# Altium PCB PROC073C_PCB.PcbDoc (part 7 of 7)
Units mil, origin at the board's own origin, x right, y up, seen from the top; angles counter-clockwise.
Board outline 2165.35 x 2695.12 mil, 8 copper layers (Top Layer, L2_GND, L3_SIGNAL 1, L4_SIGNAL 2, L5_SIGNAL 3, L6_SIGNAL 4, L7_GND, Bottom Layer), stack 55.9 mil thick; 393 components, 319 nets, 1311 pads, 1643 vias.
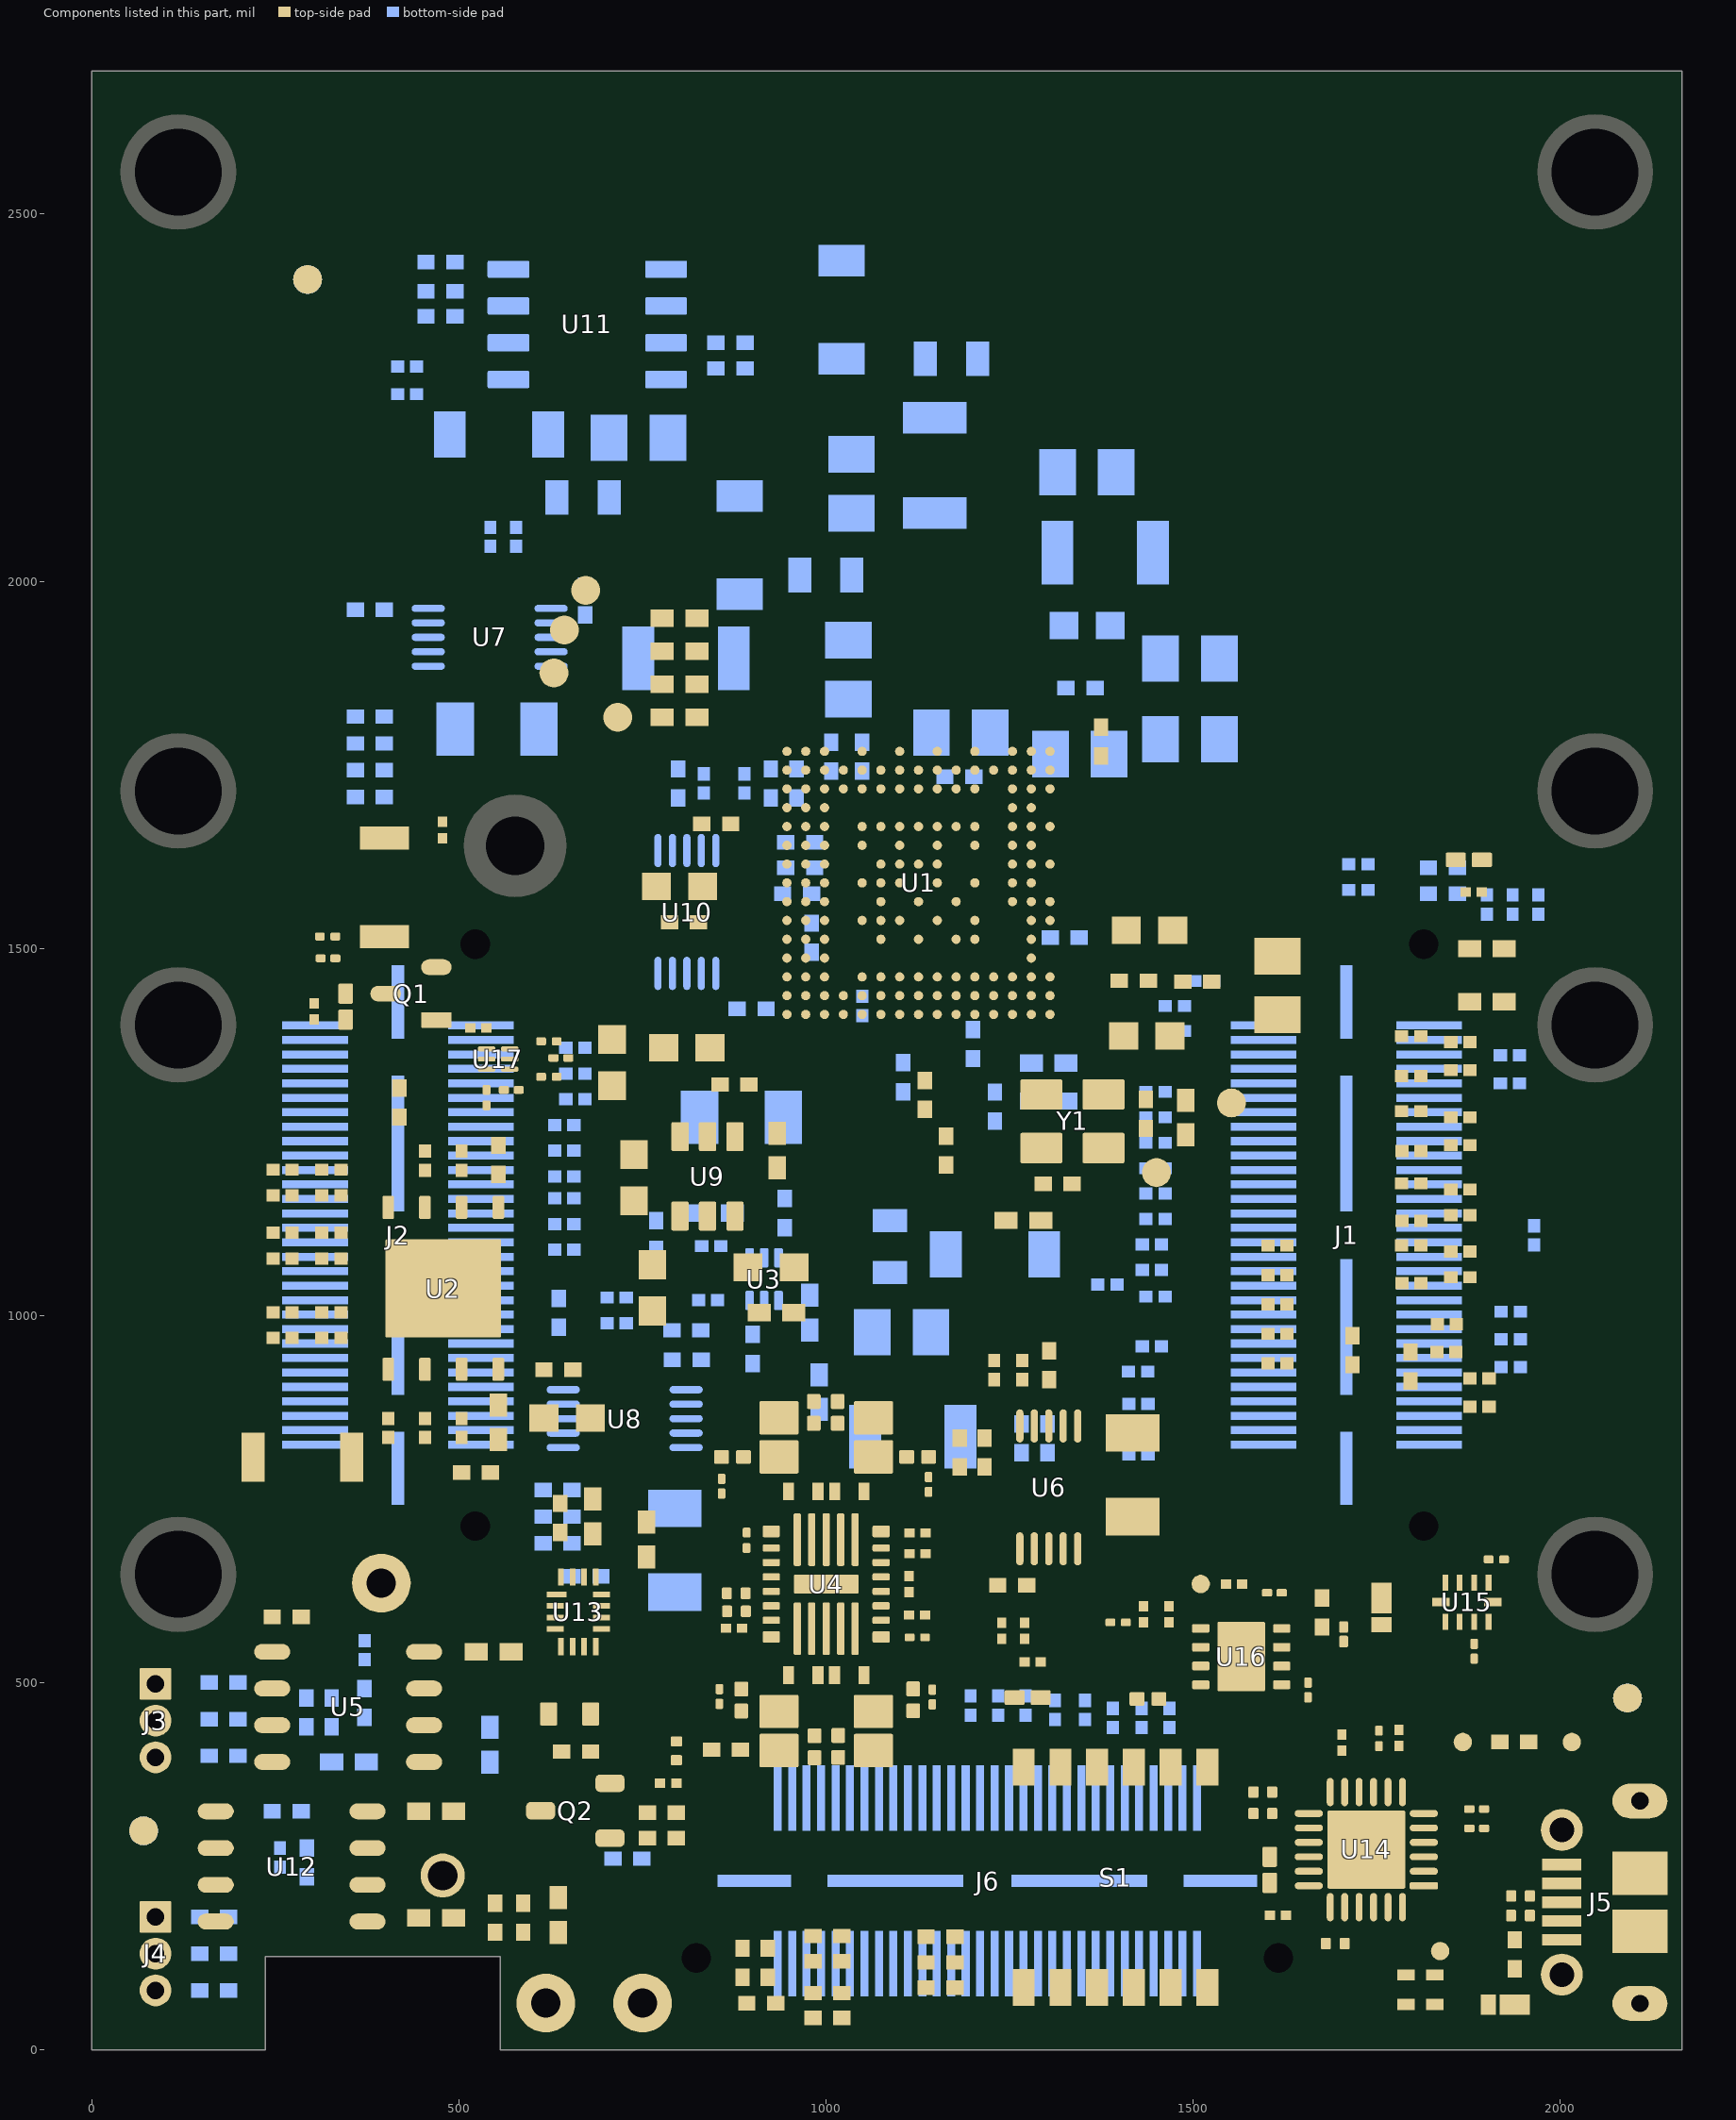
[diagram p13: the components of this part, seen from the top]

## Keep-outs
L2_GND:
  circle w1: c1074.8,1742.93 r7.87
  circle w1: c1177.16,1742.93 r7.87
  circle w1: c1125.98,1742.93 r7.87
  circle w1: c1279.52,1589.39 r7.87
  circle w1: c1279.52,1691.75 r7.87
  circle w1: c1279.52,1640.57 r7.87
  circle w1: c522.48,1506.29 r32
  circle w1: c1023.62,1742.93 r7.87
L3_SIGNAL 1:
  circle w1: c522.48,1506.29 r32
L5_SIGNAL 3:
  circle w1: c522.48,1506.29 r30
L7_GND:
  circle w1: c522.48,1505.29 r32
Bottom Layer:
  circle w1: c522.48,1506.29 r27.7
Keep-Out Layer:
  circle w1: c823.48,125.36 r32
  circle w1: c1616,125.36 r32
  circle w1: c522.48,1505.77 r32
  circle w1: c1813.86,1506.03 r32
  circle w1: c1813.86,713.51 r31
  circle w1: c522.48,713.25 r32
  lines w10: -5,-5 241.54,-5 241.54,122.3 551.54,122.3 551.54,-5 2170.35,-5 2170.35,2700.12 -5,2700.12 -5,-5
  text ".Layer_Name" at -423,-1328.72 h60

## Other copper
Top Layer:
  pour cut-out: 1039.36,1742.93 cw(c1023.62,1742.93) 1023.62,1727.19 cw(c1023.62,1742.93) 1007.88,1742.93 cw(c1023.62,1742.93) 1023.62,1758.67 cw(c1023.62,1742.93)
  pour cut-out: 1090.54,1742.93 cw(c1074.8,1742.93) 1074.8,1727.19 cw(c1074.8,1742.93) 1059.06,1742.93 cw(c1074.8,1742.93) 1074.8,1758.67 cw(c1074.8,1742.93)
  pour cut-out: 1141.72,1742.93 cw(c1125.98,1742.93) 1125.98,1727.19 cw(c1125.98,1742.93) 1110.24,1742.93 cw(c1125.98,1742.93) 1125.98,1758.67 cw(c1125.98,1742.93)
  pour cut-out: 1192.9,1742.93 cw(c1177.16,1742.93) 1177.16,1727.19 cw(c1177.16,1742.93) 1161.42,1742.93 cw(c1177.16,1742.93) 1177.16,1758.67 cw(c1177.16,1742.93)
  pour cut-out: 1295.26,1691.75 cw(c1279.52,1691.75) 1279.52,1676.01 cw(c1279.52,1691.75) 1263.78,1691.75 cw(c1279.52,1691.75) 1279.52,1707.49 cw(c1279.52,1691.75)
  pour cut-out: 1295.26,1640.57 cw(c1279.52,1640.57) 1279.52,1624.83 cw(c1279.52,1640.57) 1263.78,1640.57 cw(c1279.52,1640.57) 1279.52,1656.31 cw(c1279.52,1640.57)
  pour cut-out: 1295.26,1589.39 cw(c1279.52,1589.39) 1279.52,1573.65 cw(c1279.52,1589.39) 1263.78,1589.39 cw(c1279.52,1589.39) 1279.52,1605.13 cw(c1279.52,1589.39)
  text ".Layer_Name" at -423,-1328.72 h60
L2_GND:
  pour cut-out: 1031.49,1742.93 cw(c1023.62,1742.93) 1023.62,1735.06 cw(c1023.62,1742.93) 1015.75,1742.93 cw(c1023.62,1742.93) 1023.62,1750.8 cw(c1023.62,1742.93)
  pour cut-out: 1031.49,1742.93 cw(c1023.62,1742.93) 1023.62,1735.06 cw(c1023.62,1742.93) 1015.75,1742.93 cw(c1023.62,1742.93) 1023.62,1750.8 cw(c1023.62,1742.93)
  pour cut-out: 2140.93,1894.21 1997.92,1894.21 1885.11,1781.4 1885.11,1752.99 1682.7,1550.58 1621.63,1550.58 1392.37,1550.58 1354.68,1512.89 1354.68,1435.56 1354.68,1349.14 1374.9,1349.14 1374.9,1459.96 1374.9,1502.39 1400.28,1527.77 1691.88,1527.77 1908.35,1744.24 1908.35,1769.33 2011.45,1872.43 2140.93,1872.43
  pour cut-out: 1236.78,1369.53 1245.87,1378.63 1245.87,1390.9 1075.37,1561.4 1075.37,1583.56 1033,1625.93 1033,1675.19 1014.95,1693.24 977.13,1731.06 977.13,1803.28 809.63,1970.78 809.63,2674.62 788,2674.62 788,1960.17 956.28,1791.89 956.28,1718.82 1012.83,1662.27 1012.83,1612.65 1057.82,1567.66 1057.82,1548.49
  pour cut-out: 1250,1352.77 1236,1338.77 1236,1209.77 1257,1188.77 1257,1150.77 1263,1144.77 1320,1144.77 1344,1168.77 1403,1168.77 1411,1176.77 1411,1201.77 1433,1223.77 1462,1223.77 1470,1231.77 1470,1308.77 1435,1343.77 1373,1343.77 1373,1362.77 1454.66,1362.77 1486.15,1331.27 1486.15,1227.06 1465.09,1206 1444.23,1206 1426,1187.77 1426,1179.77 1397,1150.77 1354.51,1150.78 1329.44,1125.71 1257.05,1125.71 1236.03,1146.74 1236.02,1187.55 1216.02,1207.57 1216.02,1348.77 1230.01,1362.76 1249.76,1362.77
  pour cut-out: 1218.81,1203.66 1218.81,1187.87 1213.48,1182.54 1221.37,1174.65 1227.89,1174.65 1227.89,1179.98 1236.96,1189.06 1224.73,1201.29 1224.73,1203.07
  pour cut-out: 1029,1690.77 1044,1690.77 1044,1675.53 1041.24,1672.77 1023,1672.77 1023,1684.77
  pour cut-out: 1060,1506.93 1075,1506.93 1075,1491.7 1072.23,1488.93 1054,1488.93 1054,1500.93
  pour cut-out: 1085.74,1504.93 1100.74,1504.93 1100.74,1489.7 1097.97,1486.93 1079.74,1486.93 1079.74,1498.93
  pour cut-out: 1255,1524.93 1270,1524.93 1270,1509.7 1267.23,1506.93 1249,1506.93 1249,1518.93
  pour cut-out: 1023.84,1565.52 1023.84,1580.52 1039.07,1580.52 1041.84,1577.75 1041.84,1559.52 1029.84,1559.52
  pour cut-out: 1031,1630.93 1046,1630.93 1046,1615.7 1043.23,1612.93 1025,1612.93 1025,1624.93
  pour cut-out: 885,1561.12 900,1561.12 900,1545.88 897.23,1543.12 879,1543.12 879,1555.12
  pour cut-out: 1158.84,1677.77 1158.84,1692.77 1174.07,1692.77 1176.84,1690 1176.84,1671.77 1164.84,1671.77
  pour cut-out: 1225.74,1492.7 1240.95,1499.13 1243.46,1488.94 1244.87,1485.02 1229.98,1477.34 1225.59,1492.23
  pour cut-out: 1223.69,1493.92 1242.47,1501.17 1246.63,1484.33 1229.52,1475.52 1223.69,1493.14
  text ".Layer_Name" at -423,-1328.72 h60
L3_SIGNAL 1:
  pour cut-out: 1180.53,1695.24 1183,1692.77 1178.14,1687.91 1178.14,1674.63 1173.94,1670.44 1154.33,1670.44 1146.87,1677.9 1146.87,1683.84 1158.27,1695.24
  text ".Layer_Name" at -423,-1328.72 h60
L5_SIGNAL 3:
  text ".Layer_Name" at -423,-1328.72 h60
L7_GND:
  pour cut-out: 885.48,1168.36 885.48,1170.93 891.89,1177.34 897.35,1177.34 906.33,1168.36 898.95,1160.98 898.95,1158.1 895.1,1158.1 886.44,1166.76
  pour cut-out: 1743.38,938.01 1743.38,940.58 1749.79,946.99 1755.25,946.99 1764.23,938.01 1756.85,930.63 1756.85,927.75 1753,927.75 1744.34,936.41
  pour cut-out: 1048,1510.83 1021.98,1510.83 1021.98,1528.36 1048,1528.36
  pour cut-out: 1048.65,1562.03 1022.63,1562.03 1022.63,1579.56 1048.65,1579.56
  pour cut-out: 1022.8,1633.29 1048.81,1633.29 1048.81,1615.75 1022.8,1615.75
  pour cut-out: 1180.98,1673.77 1154.96,1673.77 1154.96,1691.31 1180.98,1691.31
  pour cut-out: 1064,1508.77 1080,1492.77 1080,1488.77 1071,1479.77 1068,1479.77 1052,1495.77 1052,1502.77 1059,1509.77 1062,1509.77
  text ".Layer_Name" at -423,-1328.72 h60
L4_SIGNAL 2:
  pour cut-out: 606.77,105.29 595.32,105.29 574.71,84.69 574.71,36.35 598.01,13.06 640.51,13.06 664.11,36.66 664.11,80.28 640.51,103.88
  text ".Layer_Name" at -423,-1328.72 h60
L6_SIGNAL 4:
  text ".Layer_Name" at -423,-1328.72 h60
Bottom Layer:
  pour cut-out: 263,2442.77 317,2496.77 880,2496.77 908,2468.77 908,2406.77 893,2391.77 274,2391.77 263,2402.77
  text ".Layer_Name" at -423,-1328.72 h60
Multi-Layer:
  pour cut-out: 211.71,19.19 211.71,154.89 586.6,154.89 586.6,19.19
  pour cut-out: 29.94,27.55 2140,27.55 2140,2673.77 30,2673.77 29.99,0 0,0 0,2695.13 2165.35,2695.12 2165.35,-0.01 29.94,0

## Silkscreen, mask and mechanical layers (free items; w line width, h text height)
Top Overlay:
  circle w10: c1851.26,218.12 r4.23
  rectangle: 24.14,216.24 52.92,231
  rectangle: 24.14,533.58 52.92,548.34
  lines w6: 180,744.77 220,744.77 220,644.77 ; 187.08,956.71 187.08,971.8 216.47,1001.19 ; 203.5,1206.1 198.92,1201.52 198.92,1095 214.76,1079.16 ; 359.1,939.04 371.21,951.15 371.21,991.64 364.91,997.95 ; 383.71,774.67 383.71,795.43 395.39,807.12 ; 522.4,204.96 527.4,209.97 527.4,213.05 ; 650.06,1337.19 662.26,1324.99 662.26,1238.78 ; 657.67,112.12 706.66,161.11 712.03,161.11 ; 675.82,2195.2 675.82,2041.71 744.05,2041.71 ; 761.66,2059.3 761.66,2193.97 ; 774.75,2062.58 794.98,2042.34 794.98,1983.12 ; 821.46,509.48 866.94,509.48 871.21,505.2 ; 890.13,517.17 902.42,504.88 932.08,504.88 ; 895.08,252.69 923.22,224.55 923.22,162.64 ; 1024.9,286.07 1033.92,277.05 1033.92,176.32 ; 1073.36,509.11 1102.17,509.11 1110.02,516.96 1152.89,516.96 1164.63,505.21 ; 1151.44,255.15 1173.87,232.72 1173.87,176.09 ; 1432.01,1236.14 1432.01,1218.99 1398.09,1185.07 ; 1432.32,544.63 1432.32,565.81 ; 1464.36,621.82 1464.36,635.6 1473.8,645.04 ; 1622.2,322.74 1630.02,330.56 1630.02,346.86 ; 1636.74,202.78 1651.26,188.26 1651.26,101.82 1647.25,97.82 ; 1750.24,113.65 1762.5,125.91 1811.19,125.91 1816.96,120.13 ; 1398.09,1185.07 1408.09,1185.07 1398.09,1195.07 1398.09,1185.07
  text "PROC073    REV C" at 306.02,1784.69 h45 r90
  text ".Layer_Name" at -423,-1328.72 h60
Bottom Overlay:
  circle w6: c1519.56,2258 r30
  circle w6: c696.91,1785.21 r30
  circle w6: c667.74,1444.28 r30
  circle w6: c306.34,2330.37 r30
  lines w6: 195.77,212.35 211.03,197.1 211.03,105.23 203.95,98.16 ; 230.93,1357.2 249.25,1375.52 ; 260.27,1989.62 367.53,1989.62 367.53,2282.85 ; 590.66,584.68 616.35,610.38 616.35,673.36 ; 618.56,1067.04 677.15,1067.04 677.71,1067.6 677.71,1262.72 698.6,1283.61 698.6,1390.14 638.79,1390.14 ; 722.34,1762.94 734.1,1751.18 775.46,1751.18 ; 779.7,1693.59 779.7,1764.78 949.23,1764.78 983.54,1799.1 1073.68,1799.1 1073.68,1727.91 1062.42,1716.64 997.88,1716.64 ; 849.15,976.93 869.4,956.68 869.4,912.82 ; 911.78,1611.9 925.28,1611.9 ; 915.72,1104.36 915.72,1171.8 ; 1466.32,2281.97 1437.37,2281.97 1437.37,2399.92 1681.03,2399.92 1681.03,2318.71 1681.03,2286.01 1570.18,2286.01 ; 1541.94,1998.64 1551.13,1989.45 1551.13,1951.61 ; 1864.28,1553.9 1864.28,1531.69 1900.82,1495.15 ; 1872.86,823.99 1888.58,808.27 1888.54,766.33 ; 1551.13,1951.61 1561.13,1961.61 1541.13,1961.61 1551.13,1951.61
  text "A" at 323.27,2314.67 h50
  text "B" at 1531.31,2241.14 h50
  text "B" at 708.67,1768.34 h50
  text "5V_IN" at 480.84,1549.08 h45
  text "A" at 684.67,1428.58 h50
  text "60" at 1938.04,1425.96 h60
  text "5V_IN" at 220.8,1394.53 h50 r270
  text "VPP_1P7" at 219.08,1201.14 h40 r270
  text "1V8" at 1546.29,889.46 h40
  text "1V2" at 1546.95,858.31 h40
  text "3V3" at 1939.64,839.01 h40
  text "1V0" at 1544.85,820.63 h40
  text "2" at 589.41,815.57 h40
  text "1" at 228.35,806.24 h40
  text "5V_IN" at 1957.22,730.57 h40
  text "1" at 1549.43,697.41 h60
  text "TEXAS" at 1484.42,658.92 h70
  text "INSTRUMENTS" at 1583.13,602.59 h70
  text ".Layer_Name" at -423,-1328.72 h60
Top Paste:
  text ".Layer_Name" at -423,-1328.72 h60
Bottom Paste:
  text ".Layer_Name" at -423,-1328.72 h60
Top Solder:
  rectangle: 33,2534.77 900,2673.77
  region: 170.16,1130.45 161.98,1122.27 161.98,1060.26 170.16,1053.01 170.16,737.97 208.1,700.03 208.1,549.95 30,549.95 30,2673.77 212.31,2673.77 212.31,1340.37 170.16,1298.22
  region: 1952.32,597.96 1966.41,583.86 1966.41,557.33 1973.96,549.78 2140,549.94 2140,2673.77 1960,2673.77 1960,1344.77 2015,1289.77 2015,774.77 1952.32,712.08
  text ".Layer_Name" at -423,-1328.72 h60
  text ".Layer_Name" at -423,-1328.72 h60
Bottom Solder:
  region: 1955.84,595.06 1967.77,583.13 1967.77,557.86 1975.39,550.25 2140,549.94 2140,2673.77 30,2673.77 30,549.95 214.94,549.95 215.12,719.64 170,764.76 170,1295.98 205,1330.98 205,1642.77 241,1678.77 241,2421.06 335.84,2515.9 1940,2515.9 1940,1748.77 2019.99,1668.77 2020,1500.76 1962.25,1443.02 1962.25,1357.17 2015.39,1304.03 2015.39,765.16 1955.85,705.61
  region: 1911.1,1755.67 1937.91,1755.3 2022.09,1671.12 2022.09,1664.79 2021.72,1664.42 1937.12,1664.42 1902.9,1698.64 1902.9,1747.47
  text ".Layer_Name" at -423,-1328.72 h60
Drill Guide:
  text ".Layer_Name" at -423,-1328.72 h60
M1 Board Outline:
  the board outline again, w10
  text ".Layer_Name" at -423,-1328.72 h60
M2 Board Dimensions:
  rectangle: -1000,-745.23 -875,-620.23
  rectangle: -875,-870.23 -500,-745.23
  lines w7: -1000,-745.23 0,-745.23 ; -875,-870.23 -875,-620.23 ; -750,-870.23 -750,-620.23 ; -500,-870.23 -500,-620.23 ; -250,-870.23 -250,-620.23 ; -1000,-870.23 0,-870.23 0,-620.23 -1000,-620.23 -1000,-870.23
  text ".Layer_Name" at -434.88,-1326.78 h60
M3 3D STEP Top:
  text ".Layer_Name" at -423,-1328.72 h60
M4 3D STEP Bottom:
  text ".Layer_Name" at -423,-1328.72 h60
M5 Assembly Top:
  lines w10: -1292,-1400.4 5308,-1400.4 ; -1292,-1197.06 5310,-1197.06 ; -1292,-993.73 -1292,-1603.73 2713,-1603.73 5310,-1603.73 5310,-993.73 -1291.5,-993.73 -1291.5,-1603.73 284,-1603.73 ; 1173,-1603.73 1173,-993.73 ; 2440,-1197.06 2440,-993.73 ; 3280,-1197.06 3280,-993.73 ; 3902,-1610.23 3902,-1407.4
  text "COMPONENTS MARKED 'DNP' SHOULD NOT BE POPULATED." at 153.5,-788.73 h60
  text "ASSEMBLY VARIANT:" at 153,-904.23 h60
  text ".VariantName" at 1189,-904.23 h60
  text "PCB VIEWED FROM TOP SIDE" at -1228.5,-1125.9 h60
  text "BOARD #:" at 1248,-1125.9 h60
  text ".PRJ_Number" at 1793.5,-1125.9 h60
  text "REV:" at 2638,-1125.9 h60
  text ".PCB_Rev" at 2929.5,-1125.9 h60
  text "SVN REV:" at 3476,-1125.9 h60
  text ".VersionControl_RevNumber" at 3982,-1125.9 h60
  text "Assembly Layer Top" at -433,-1325.23 h60
  text "TID #:" at 1248,-1329.23 h60
  text ".TID" at 1793.5,-1329.23 h60
  text "PLOT NAME =" at -1228.5,-1534.57 h60
  text ".plot_File_Name" at -423,-1534.57 h60
  text "GENERATED    :" at 1250,-1534.57 h60
  text ".Print_Date" at 2119.5,-1534.57 h60
  text ".Print_Time" at 2848.5,-1534.57 h60
  text "TEXAS INSTRUMENTS" at 4113,-1534.57 h60
M6 Assembly Bottom:
  lines w6: 705,1254.77 705,1394.77 ; 786.98,1167.48 791.01,1163.45 791.01,1113.45 810.46,1094 810.46,1101.2 802.41,1093.15 809.61,1093.15 ; 833.84,1760.54 833.84,1778.03 ; 1770.26,1663.38 1770.26,1605.73 1798.64,1577.34 1798.64,1587.22 1788.68,1577.25 1796.09,1577.25 ; 705,1394.77 714.25,1385.52 695.75,1385.52 705,1394.77
  lines w10: -1292.5,-1197.56 5309.5,-1197.56 ; -1290.5,-1400.9 5309.5,-1400.9 ; 115.5,-1610.73 115.5,-1407.9 ; 737.5,-1197.56 737.5,-994.23 ; 1577.5,-1197.56 1577.5,-994.23 ; 2844.5,-1604.23 2844.5,-994.23 ; 3733.5,-1604.23 5309,-1604.23 5309,-994.23 -1292.5,-994.23 -1292.5,-1604.23 1304.5,-1604.23 5309.5,-1604.23 5309.5,-994.23
  text "59" at 350,1394.77 h45
  text "60" at 530.04,1395.21 h45
  text "59" at 1636,1395.2 h45
  text "60" at 1821.54,1395.2 h45
  text "1" at 325,804.77 h45
  text "2" at 525,804.77 h45
  text "1" at 1611,794.77 h45
  text "2" at 1822,794.77 h45
  text "COMPONENTS MARKED 'DNP' SHOULD NOT BE POPULATED." at 5102,-788.23 h60
  text ".VariantName" at 4058,-904.23 h60
  text "ASSEMBLY VARIANT:" at 5097,-904.23 h60
  text ".VersionControl_RevNumber" at 35.5,-1126.4 h60
  text "SVN REV:" at 541.5,-1126.4 h60
  text ".PCB_Rev" at 1088,-1126.4 h60
  text "REV:" at 1379.5,-1126.4 h60
  text ".PRJ_Number" at 2224,-1126.4 h60
  text "BOARD #:" at 2769.5,-1126.4 h60
  text "PCB VIEWED FROM BOTTOM SIDE" at 5246,-1126.4 h60
  text "Assembly Bottom Layer" at 4885,-1315.23 h60
  text ".TID" at 2224,-1329.73 h60
  text "TID #:" at 2769.5,-1329.73 h60
  text "TEXAS INSTRUMENTS" at -95.5,-1535.07 h60
  text ".Print_Time" at 1169,-1535.07 h60
  text ".Print_Date" at 1898,-1535.07 h60
  text "GENERATED    :" at 2767.5,-1535.07 h60
  text ".plot_File_Name" at 4440.5,-1535.07 h60
  text "PLOT NAME =" at 5246,-1535.07 h60
M7 LPKF Text Top:
  lines w2: 1007.88,1742.93 1039.36,1742.93 ; 1015.75,1742.93 1031.49,1742.93 ; 1023.62,1727.19 1023.62,1758.67 ; 1023.62,1735.06 1023.62,1750.8
M9 Title Sheet:
  drawing of 57 lines, arcs and shapes, not listed
  text "1" at -260.16,7566.27 h70
  text "2" at 2235.5,7566.27 h70
  text "3" at 4724.84,7566.27 h70
  text "4" at 7231.51,7566.27 h70
  text "5" at 9730.5,7566.27 h70
  text "6" at 12235.5,7566.27 h70
  text "A" at -1416.5,6423.27 h70
  text "A" at 13383.5,6423.27 h70
  text "B" at -1416.5,4043.27 h70
  text "B" at 13383.5,4043.27 h70
  text "C" at -1416.5,1668.27 h70
  text "C" at 13383.5,1668.27 h70
  text "PROJECT TITLE:" at 10343.5,-192.73 h45
  text ".PRJ_Title" at 10393.5,-326.06 h70
  text "DESIGNED FOR:" at 10343.5,-493.73 h45
  text ".PRJ_Customer" at 10393.5,-633.73 h70
  text "D" at -1416.5,-701.73 h70
  text "D" at 13383.5,-701.73 h70
  text "FILE NAME:" at 10343.5,-793.73 h45
  text ".PCB_File_Name_No_Path" at 10393.5,-913.73 h70
  text "Texas Instruments (TI) and/or its licensors do not warrant the accuracy or completeness of this specification" at 5374,-1075.57 h45
  text "ENGINEER:" at 10343.5,-1083.73 h45
  text "LAYOUT BY:" at 11848.5,-1083.73 h45
  text "or any information contained therein. TI and/or its licensors do not warrant that this design will meet" at 5329.01,-1188.23 h45
  text ".PRJ_Engineer" at 10393.5,-1238.72 h70
  text ".PCB_Layout" at 11899,-1238.72 h70
  text "the specifications, will be suitable for your application or fit for any particular purpose, or will operate in" at 5329.01,-1300.9 h45
  text ".Layer_Name" at -413.7,-1335.71 h60
  text "ALTIUM DESIGNER VERSION:" at 11848.5,-1393.73 h45
  text "an implementation. TI and/or its licensors do not warrant that the design is production worthy. You should" at 5329.01,-1413.56 h45
  text "completely validate and test your design implementation to confirm the system functionality for your application." at 5374,-1526.23 h45
  text ".print_Scale" at 10393.5,-1527.06 h70
  text ".Application_BuildNumber" at 11899,-1527.06 h70
  text "1" at -260.16,-1733.73 h70
  text "2" at 2235.5,-1733.73 h70
  text "3" at 4724.84,-1733.73 h70
  text "4" at 7231.51,-1733.73 h70
  text "5" at 9730.5,-1733.73 h70
  text "WO # : 308145-8143-D" at 12235.5,-1733.73 h70
M10 Fab Notes:
  drawing of 198 lines, arcs and shapes, not listed
  text "DESIGN INFORMATION" at 11382.02,5885.94 h60
  text "MIN. TRACK WIDTH:" at 10737.46,5753.82 h60
  text "4" at 11833.7,5753.82 h60
  text "MIL" at 11988.46,5753.82 h60
  text "3.9" at 11781.69,5636.97 h60
  text "MIN. CLEARANCE:" at 10737.46,5629.69 h60
  text "MIL" at 11988.46,5629.69 h60
  text "MIN. VIA PAD SIZE:" at 10737.46,5505.57 h60
  text "13.77" at 11679,5500.77 h60
  text "MIL" at 12011,5496.77 h60
  text "EXTERNAL" at 12258.6,5378.26 h60
  text "0.0508mm (2.0MIL)" at 11432.46,5375.67 h60
  text "MINIMUM ANNULAR RING" at 10408.23,5367.44 h60
  text "PER" at 10608.23,5257.32 h60
  text "IPC-D-275 CLASS 2 LEVEL C" at 10828.23,5257.31 h60
  text "MIL, HOLES" at 12316.46,5156.84 h60
  text "+/-" at 11924,5148.25 h60
  text "+/-" at 12778,5148.25 h60
  text "REGISTRATION TOLERANCES:" at 10408.23,5147.19 h60
  text "METAL" at 11608,5147.19 h60
  text "5" at 12184.2,5147.19 h60
  text "3" at 13017.2,5147.19 h60
  text "MIL" at 13133.46,5147.19 h60
  text "HOLE SIZE TOLERANCE (UNLESS OTHERWISE SPECIFIED):" at 10408.23,5048.87 h60
  text "+/-" at 12778,5046 h60
  text "3" at 13017.2,5044.94 h60
  text "MIL" at 13133.46,5044.94 h60
  text "MATERIAL:" at 10333.46,4907.29 h60
  text "FR-4 High Tg" at 11319.9,4778.77 h60
  text "X" at 12062,4773.77 h60
  text "REFER STACK-UP" at 12562.85,4773.18 h55
  text "FR-408" at 10754.46,4766.26 h60
  text "OTHER" at 12242.46,4766.26 h60
  text "X" at 12233,4625.78 h60
  text "62 MIL (1.6mm) +/-10%" at 11074.56,4623.23 h60
  text "57.37 MIL +/-10%" at 12655,4616.77 h45
  text "THICKNESS:" at 10408.23,4615.01 h60
  text "OTHER" at 12359.46,4615.01 h60
  text "TOLERANCE:" at 10408.23,4476.69 h60
  text "X" at 11256.46,4476.69 h60
  text "ANSI IPC-6012 TYPE 3 CLASS 2" at 11434.48,4476.69 h60
  text "OTHER +/-" at 11434.46,4332.5 h60
  text "BOW & TWIST:" at 10408.23,4187.31 h60
  text "X" at 11256.46,4187.31 h60
  text "ANSI IPC-6012 TYPE 3 CLASS 2" at 11434.48,4187.31 h60
  text "OTHER +/-" at 11434.46,4040.62 h60
  text "DRILLING:" at 10333.46,3910 h60
  text "NC_DRILL FILES" at 12094.46,3804.81 h60
  text "REFERENCE:" at 10408.23,3800.87 h60
  text "X" at 11065.46,3800.78 h60
  text "AS SHOWN" at 11243.46,3800.87 h60
  text "X" at 11966.46,3800.87 h60
  text "OTHER" at 12392.46,3658.62 h60
  text "PTH COPPER THICKNESS:" at 10407.91,3655.09 h60
  text "X" at 11547.14,3655.09 h60
  text "20-30 um" at 11675.14,3655.09 h60
  text "BOARD FINISH:" at 10333.46,3507.5 h60
  text "SILKSCREEN:" at 10488.68,3397.37 h60
  text "X" at 11446.46,3397.37 h60
  text "TOP" at 11563.46,3397.37 h60
  text "X" at 11956.46,3397.37 h60
  text "BOTTOM" at 12074.46,3397.37 h60
  text "SILKSCREEN COLOR:" at 10488.68,3242.18 h60
  text "X" at 11445.46,3242.18 h60
  text "WHITE" at 11563.46,3242.18 h60
  text "OTHER" at 12074.46,3242.18 h60
  text "GREEN" at 11694.46,3098.73 h60
  text "X" at 12168.46,3098.73 h60
  text "OTHER" at 12312.46,3098.73 h60
  text "RED" at 12685,3098.73 h60
  text "SOLDER RESIST COLOR:" at 10488.68,3091.87 h60
  text "MATTE" at 11694.46,2944.48 h60
  text "SEMI-GLOSS" at 12312,2943.84 h60
  text "X" at 12168.06,2941.79 h60
  text "IMMERSION GOLD (ENIG)" at 11394.46,2771.71 h60
  text "ENEPIG" at 12732,2764.49 h60
  text "SURFACE FINISH:" at 10333.46,2763.49 h60
  text "IMM. TIN/SILVER OR EQUIV" at 10663,2626.17 h60
  text "X" at 10510,2623.49 h60
  text "OTHER" at 12094.46,2622.24 h60
  text "NOTES:" at 3534.49,2497.33 h60
  text "ARRAY/PANEL:" at 10333.46,2466.86 h60
  text "CUT AND TRIM PER M1 BOARD OUTLINE" at 11394.46,2458.64 h60
  text "N.C. ROUTE" at 11394.46,2322.67 h60
  text "X" at 12082.46,2322.67 h60
  text "V. SCORE" at 12260.46,2322.67 h60
  text "1. VIA'S ON PAD AND BGA PACKAGE AREA SHOULD BE FILLED WITH CONDUCTIVE MATERIAL AND SURFACE SHOULD BE FLAT" at 3563.63,2322.16 h60
  text "BGA AREA VIAS SHOULD BE CAPPED WITH COPPER PLATING TO ENSURE FLAT SURFACE" at 3670.36,2215.01 h60
  text "CERTIFICATION:" at 10333.46,2193.54 h60
  text "MATERIALS AND WORKMANSHIP FOR ALL PCBS" at 11058.46,2193.54 h60
  text "FLATNESS TOLERANCE FOR VIA ON PADS: +0.000 /- 0.001 INCHES ON BOTH SIDES." at 3670.36,2116.43 h60
  text "TO MEET OR EXCEED THE REQUIREMENTS OF:" at 11058.46,2099.48 h60
  text "OTHER THAN BGA AND VIA'S ON THE PAD  VIA FILLING REQUIREMENT CAN BE EXMPTED" at 3670.36,2006.42 h60
  text "X" at 10695.97,1970.85 h60
  text "ANSI IPC-A-600F CLASS ->" at 10823.96,1970.85 h60
  text "X" at 12471.97,1970.85 h60
  text "2" at 12581.96,1970.85 h60
  text "1" at 12266.96,1969.35 h60
  text "3" at 12935.96,1969.35 h60
  text "2. VENDOR MAY ADJUST SOLDERMASK WHEREVER SOLDERMASK PADS ARE THE SAME SIZE (1:1) AS PER THE MANUFACTURING CAPABILITIES" at 3563.63,1878.75 h60
  text "X" at 11507.97,1823.16 h60
  text "RoHS" at 11635.96,1823.16 h60
  text "OTHER" at 12280.36,1823.16 h60
  text "PER ORDER" at 12677.42,1823.16 h60
  text "AND ALL OTHER SOLDER MASK PADS SHALL NOT BE MODIFIED, PROVIDED NO ADJACENT COPPER IS EXPOSED AND NO CONFLICT IS PRODUCED" at 3670.36,1779.75 h60
  text "WITH ANY STATED \"VIA TENTING/COVERING\" REQUIREMENTS." at 3670.36,1686.47 h60
  text "ALL BOARDS MUST MEET OR EXCEED UL94-V0 REQUIREMENTS." at 10361,1669.34 h60
  text "PCB MUST BEAR THE UL94V-0 UL REGISTERED MATERIAL ID NUMBER" at 10361,1553.27 h60
  text "3. MANUFACTURER'S IDENTIFICATION,DATECODE LETTER SHALL BE SILKSCREENED ON SOLDER SIDE OF THE BOARD." at 3563.63,1525.38 h60
  text "ADDITIONAL REQUIREMENTS:" at 10333.46,1383.85 h60
  text "4. TRACE WIDTH SHOULD BE ACCURATELY ETCHED. MAX TOLERANCE +/- 1 MIL." at 3563.63,1375.21 h60
  text "MICROSECTION:" at 10408.23,1276.72 h60
  text "YES" at 11313.96,1276.72 h60
  text "5. LAYER TO LAYER REGISTRATION SHALL BE WITHIN +/-2 MIL." at 3563.63,1227.89 h60
  text "REQUIRED" at 12175.46,1132.39 h60
  text "BARE BOARD ELEC. TEST:" at 10408.23,1129.53 h60
  text "NONE" at 11713.96,1129.53 h60
  text "X" at 12057.46,1129.53 h60
  text "PER ORDER" at 12767.46,1129.53 h60
  text "6. REFER IMPEDANCE TABLE FOR IMPEDANCE CONTROL TRACES ON LAYER 1, 3, 6 & 8." at 3563.63,1083.43 h60
  text "XX MIL VIAS REQUIRE NON-CONDUCTIVE FILL AND PLANARIZE" at 10592,983.77 h59
  text "7. FOR ACCURACY OF THE ANTENNA DIMENSION, NEED TO BE MEASURE THE  ANTENNA DIMENSIONS ON ONE BAORD" at 3563.63,936.11 h60
  text "XX MIL VIAS REQUIRE CONDUCTIVE FILL AND PLANARIZE" at 10583,824.77 h60
  text "AS PER  ANTENNA DOCUMENT( Visio-IWR_60GHz4)." at 3670.36,815.7 h60
  text "OUTER XX MIL TRACES REQUIRE 50 OHM SINGLE-ENDED IMPEDANCE" at 10578.15,681.87 h58
  text "8. ALL VIAS ARE TENTED ON BOTH SIDES UNLESS OTHERWISE SOLDER MASK OPENED IN GERBER." at 3563.63,660.23 h60
  text "9. INTENTIONAL ONE NET ANTENNA VIA IS PRESENT IN DESIGN." at 3563.63,488.71 h60
  text "LAYER 1 & 6 (INNER LAYERS) XX MIL WIDE, XX MIL SPACE / TRACES REQUIRE 100 OHM DIFFERENTIAL IMPEDANCE" at 10617,431.77 h60
  text ".Layer_Name" at -425.59,-1329.35 h60
M11 Gerber Information:
  lines w10: -1292,-1400.4 5308,-1400.4 ; -1292,-1197.06 5310,-1197.06 ; -1292,-993.73 -1292,-1603.73 2713,-1603.73 5310,-1603.73 5310,-993.73 -1291.5,-993.73 -1291.5,-1603.73 284,-1603.73 ; 1173,-1603.73 1173,-993.73 ; 2440,-1197.06 2440,-993.73 ; 3280,-1197.06 3280,-993.73 ; 3902,-1610.23 3902,-1407.4
  text "ALL ARTWORK VIEWED FROM TOP SIDE" at -1228.5,-1125.9 h60
  text "BOARD #:" at 1248,-1125.9 h60
  text ".PRJ_Number" at 1793.5,-1125.9 h60
  text "REV:" at 2638,-1125.9 h60
  text ".PCB_Rev" at 2929.5,-1125.9 h60
  text "SVN REV:" at 3476,-1125.9 h60
  text ".VersionControl_RevNumber" at 3982,-1125.9 h60
  text "LAYER NAME =" at -1228.5,-1328.72 h60
  text "TID #:" at 1248,-1329.23 h60
  text ".TID" at 1793.5,-1329.23 h60
  text "PLOT NAME =" at -1228.5,-1534.57 h60
  text ".plot_File_Name" at -423,-1534.57 h60
  text "GENERATED    :" at 1250,-1534.57 h60
  text ".Print_Date" at 2119.5,-1534.57 h60
  text ".Print_Time" at 2848.5,-1534.57 h60
  text "TEXAS INSTRUMENTS" at 4113,-1534.57 h60
M12 Stackup:
  drawing of 562 lines, arcs and shapes, not listed
  text "LAYER STACK-UP :" at 5193.51,7078.8 h80
  text "Layer" at 5213.16,6908.54 h60
  text "Name" at 5623.08,6908.54 h60
  text "Material" at 6552.82,6908.54 h60
  text "Thickness" at 7412.59,6908.54 h60
  text "Constant" at 8062.42,6908.54 h60
  text "Board Layer Stack" at 8632.29,6908.54 h60
  text "1" at 5213.16,6788.54 h60
  text "Top Overlay" at 5623.08,6788.54 h60
  text "2" at 5213.16,6668.54 h60
  text "Top Solder" at 5623.08,6668.54 h60
  text "Solder Resist" at 6552.82,6668.54 h60
  text "0.80mil" at 7412.59,6668.54 h60
  text "1" at 8062.42,6668.54 h60
  text "6" at 5023.59,6549.65 h60
  text "3" at 5213.16,6548.54 h60
  text "Top Layer" at 5623.08,6548.54 h60
  text "Copper" at 6552.82,6548.54 h60
  text "1.60mil" at 7412.59,6548.54 h60
  text "4" at 5213.16,6428.54 h60
  text "Dielectric 1" at 5623.08,6428.54 h60
  text "RO4835 LOPRO" at 6552.82,6428.54 h60
  text "3.90mil" at 7412.59,6428.54 h60
  text "3.5" at 8062.42,6428.54 h60
  text "5" at 5213.16,6308.54 h60
  text "L2_GND" at 5623.08,6308.54 h60
  text "Copper" at 6552.82,6308.54 h60
  text "1.40mil" at 7412.59,6308.54 h60
  text "6" at 5213.16,6188.54 h60
  text "Dielectric 2" at 5623.08,6188.54 h60
  text "PCL370HR" at 6552.82,6188.54 h60
  text "5.50mil" at 7412.59,6188.54 h60
  text "4.17" at 8062.42,6188.54 h60
  text "6" at 5019.85,6071.38 h60
  text "7" at 5213.16,6068.54 h60
  text "L3_SIGNAL 1" at 5623.08,6068.54 h60
  text "Copper" at 6552.82,6068.54 h60
  text "1.40mil" at 7412.59,6068.54 h60
  text "8" at 5213.16,5948.54 h60
  text "Dielectric 3" at 5623.08,5948.54 h60
  text "PCL370HR" at 6552.82,5948.54 h60
  text "10.00mil" at 7412.59,5948.54 h60
  text "4.17" at 8062.42,5948.54 h60
  text "9" at 5213.16,5828.54 h60
  text "L4_SIGNAL 2" at 5623.08,5828.54 h60
  text "Copper" at 6552.82,5828.54 h60
  text "1.40mil" at 7412.59,5828.54 h60
  text "10" at 5213.16,5708.54 h60
  text "Dielectric 4" at 5623.08,5708.54 h60
  text "PCL370HR" at 6552.82,5708.54 h60
  text "5.50mil" at 7412.59,5708.54 h60
  text "4.17" at 8062.42,5708.54 h60
  text "11" at 5213.16,5588.54 h60
  text "L5_SIGNAL 3" at 5623.08,5588.54 h60
  text "Copper" at 6552.82,5588.54 h60
  text "1.40mil" at 7412.59,5588.54 h60
  text "12" at 5213.16,5468.54 h60
  text "Dielectric 5" at 5623.08,5468.54 h60
  text "PCL370HR" at 6552.82,5468.54 h60
  text "10.00mil" at 7412.59,5468.54 h60
  text "4.17" at 8062.42,5468.54 h60
  text "13" at 5213.16,5348.54 h60
  text "L6_SIGNAL 4" at 5623.08,5348.54 h60
  text "Copper" at 6552.82,5348.54 h60
  text "1.40mil" at 7412.59,5348.54 h60
  text "6" at 5022.17,5345.68 h60
  text "14" at 5213.16,5228.54 h60
  text "Dielectric 6" at 5623.08,5228.54 h60
  text "PCL370HR" at 6552.82,5228.54 h60
  text "5.50mil" at 7412.59,5228.54 h60
  text "4.17" at 8062.42,5228.54 h60
  text "15" at 5213.16,5108.54 h60
  text "L7_GND" at 5623.08,5108.54 h60
  text "Copper" at 6552.82,5108.54 h60
  text "1.40mil" at 7412.59,5108.54 h60
  text "16" at 5213.16,4988.54 h60
  text "Dielectric 7" at 5623.08,4988.54 h60
  text "PCL370HR" at 6552.82,4988.54 h60
  text "3.90mil" at 7412.59,4988.54 h60
  text "4.17" at 8062.42,4988.54 h60
  text "17" at 5213.16,4868.54 h60
  text "Bottom Layer" at 5623.08,4868.54 h60
  text "Copper" at 6552.82,4868.54 h60
  text "1.60mil" at 7412.59,4868.54 h60
  text "6" at 5025.35,4866.09 h60
  text "18" at 5213.16,4748.54 h60
  text "Bottom Solder" at 5623.08,4748.54 h60
  text "Solder Resist" at 6552.82,4748.54 h60
  text "0.80mil" at 7412.59,4748.54 h60
  text "1" at 8062.42,4748.54 h60
  text "19" at 5213.16,4628.54 h60
  text "Bottom Overlay" at 5623.08,4628.54 h60
  text "NOTE :" at 5225.04,4478.82 h60
  text "1. THIS IS AN IMPEDANCE CONTROLLED BOARD." at 5408.55,4373.8 h60
  text "2. EXTERNAL LAYER CU THICKNESSES ARE FINISHED THICKNESS AFTER PLATING." at 5408.55,4275.93 h60
  text "6" at 7261.89,4055.48 h60
  text "IMPEDANCE TABLE :" at 6105.5,4040.1 h80
  text "SPACING" at 6299.43,3884.35 h70
  text "LAYER" at 5549.43,3879.35 h70
  text "TRACE WIDTH" at 5814.43,3879.35 h70
  text "IMPEDANCE +/- 10%" at 6634.43,3879.35 h70
  text "REFERENCE LAYER" at 7359.43,3879.35 h70
  text "TOP" at 5584.43,3729.35 h70
  text "7.795 MILS" at 5869.43,3724.35 h65
  text "8 MILS" at 6324.43,3724.35 h65
  text "50 OHM" at 6744.43,3724.35 h65
  text "LAYER-2 (GND LAYER)" at 7309.43,3724.35 h65
  text "LAYER" at 5564.57,3510.28 h70
  text "TRACE WIDTH" at 5851.77,3509.43 h70
  text "SPACING" at 6336.77,3509.43 h70
  text "IMPEDANCE +/- 10%" at 6671.77,3509.43 h70
  text "REFERENCE LAYER" at 7396.77,3509.43 h70
  text "LAYER-2 AND" at 7510.74,3369.43 h65
  text "TOP AND" at 5529.48,3365.58 h70
  text "5.2 MILS" at 5952.73,3349.43 h65
  text "5 MILS" at 6385.52,3349.43 h65
  text "100 OHM" at 6853.75,3349.43 h65
  text "BOTTOM" at 5555.85,3296.89 h60
  text "LAYER-7" at 7581.18,3294.43 h65
  text "LAYER-2, LAYER 4 &" at 7412.84,3192.75 h65
  text "4.8 MILS" at 5951.98,3159.52 h65
  text "7.2 MIL" at 6380.02,3159.52 h65
  text "100 OHM" at 6853.75,3159.52 h65
  text "L3 & L6" at 5558.48,3158.06 h70
  text "LAYER-5, LAYER 7" at 7442.71,3122.36 h65
  text ".Layer_Name" at -423,-1328.72 h60
M13 Component Bodies Top:
  text ".Layer_Name" at -423,-1328.72 h60
M14 Component Bodies Bottom:
  text ".Layer_Name" at -423,-1328.72 h60
M15 Courtyards Top:
  text ".Layer_Name" at -423,-1328.72 h60
M16 Courtyards Bottom:
  text "NOTES: UNLESS OTHERWISE SPECIFIED." at 4550.94,4101.82 h60
  text "1. FABRICATE PER IPC-6012A CLASS 2." at 4550.94,3948.7 h60
  text "2. FOR BOARD THICKNESS AND IMPEDANCE DETAILS REFER STACKUP DOCUMENT." at 4550.94,3839.82 h60
  text "3. PRINTED WIRING BOARD SHALL COMPLY WITH REQUIREMENTS OF ANSI/J-STD-003." at 4550.94,3722.82 h60
  text "4. SURFACE FINISH:IMMERSION SILVER" at 4550.94,3606.82 h60
  text "5. SOLDERMASK ON BOTH SIDES OF THE BOARD SHALL BE LPI, COLOR RED." at 4550.94,3488.82 h60
  text "6. SILK SCREEN LEGEND TO BE APPLIED PER LAYER STACKUP USING WHITE" at 4550.94,3359.82 h60
  text "NON-CONDUCTIVE EPOXY INK." at 4670.94,3246.82 h60
  text "7. THIS PRINTED WIRING BOARD IS DESIGNED WITH A MINIMUM CONDUCTOR" at 4550.94,3126.82 h60
  text "WIDTH AND SPACING OF 4 MIL &  4 MILS." at 4720.94,3003.82 h60
  text "8. ALL VIAS ARE TENTED ON BOTH SIDES UNLESS SOLDERMASK OPENED IN GERBER." at 4550.94,2889.82 h60
  text "9. ALL VIAS ON PAD INCLUDING BGA AREA SHOULD BE FILLED WITH NON CONDUCTIVE EPOXY AND SURFACE SHOULD BE FLAT" at 4550.94,2740.82 h60
  text "BGA AREA VIAS SHOULD BE CAPPED WITH COPPER PLATING TO ENSURE FLAT SURFACE" at 4720.94,2633.82 h60
  text "REFER VIA FILL DOCUMENT TO IDENTIFY THE VIAS TO BE FILLED" at 4720.94,2529.82 h60
  text "FLATNESS TOLERANCE FOR VIA ON PADS: +0.000 /- 0.001 INCHES ON BOTH SIDES." at 4720.94,2420.82 h60
  text "10. SOLDER MASK OPENING IS KEPT SAME SIZE AS PAD (1:1)" at 4550.94,2300.82 h60
  text "THE MANUFACTURER IS REQUESTED TO RESIZE IT AS PER THEIR SOLDERMASK TOLERANCE EXCEPT NPTH DRILL AND FIDUCIALS." at 4720.94,2198.82 h60
  text "11. VENDOR SHOULD FOLLOW ROHS COMPLIANT PROCESS AND Pb FREE FOR MANUFACTURING" at 4564.94,2093.82 h60
  text "12. MANUFACTURER'S IDENTIFICATION,DATECODE LETTER SHALL BE SILKSCREENED ON SOLDER SIDE" at 4564.94,1968.82 h60
  text "OF THE BOARD." at 4734.94,1855.82 h60
  text "13. TRACE WIDTH SHOULD BE ACCURATELY ETCHED. MAX TOLERANCE +/- 1 MIL" at 4564.94,1741.82 h60
  text "14. BOARD DIMENSIONS ARE IN MM)." at 4564.94,1602.82 h60
  text "15. BOW AND TWIST SHALL NOT EXCEED 0.7% OF LONGEST SIDE" at 4564.94,1460.82 h60
  text "16. PCB Material must meet or exceed UL94V-0 requirements." at 4564.94,1313.82 h60
  text "PCB must bear the UL94V-0 registered material ID number." at 4734.94,1211.82 h60
  text "17. LAYER TO LAYER REGISTRATION SHALL BE WITHIN +/-2 MIL" at 4564.94,1071.82 h60
  text "18. REFER STACKUP DOCUMENT FOR IMPEDANCE CONTROL TRACES ON LAYER 1." at 4564.94,933.82 h60
  text "50 OHM SINGLE ENDED AND 10OHM DIFFERENTIAL IMPEDANCE CONTROL TRACES." at 4734.94,834.82 h60
  text ".Layer_Name" at -423,-1328.72 h60
Drill Drawing:
  lines w8: -1243.55,3986.49 -1116.65,3986.49 -1116.65,4105.2 -1243.55,4105.2 -1243.55,3986.49 ; -1241.47,6087.39 -1114.58,6087.39 -1114.58,6206.09 -1241.47,6206.09 -1241.47,6087.39 ; -1241.47,6246.5 -1114.58,6246.5 -1114.58,6365.21 -1241.47,6365.21 -1241.47,6246.5 ; -1241.47,6420.23 -1114.58,6420.23 -1114.58,6538.94 -1241.47,6538.94 -1241.47,6420.23 ; -1241.47,6575.57 -1241.47,6694.27 -1114.58,6694.27 -1114.58,6575.57 -1241.47,6575.57
  lines w15: -1094.8,3966.86 4409.91,3966.86 ; -1094.8,4132.62 4409.91,4132.62 ; -1048.99,4912.4 4642.15,4912.4 ; -1048.99,6735.76 4642.15,6735.76 ; -644.32,3801.1 -644.32,4298.38 ; -598.51,4746.64 -598.51,6901.52 ; -165.78,3801.1 -165.78,4298.38 ; -119.97,4746.64 -119.97,6901.52 ; 682.97,3801.1 682.97,4298.38 ; 728.78,4746.64 728.78,6901.52 ; 1028.49,3801.1 1028.49,4298.38 ; 1074.3,4746.64 1074.3,6901.52 ; 1528.7,3801.1 1528.7,4298.38 ; 1574.51,4746.64 1574.51,6901.52 ; 2274.89,3801.1 2274.89,4298.38 ; 2323.69,4746.64 2323.69,6901.52 ; 3078,3801.1 3078,4298.38 ; 3126.8,4746.64 3126.8,6901.52 ; 3860.33,3801.1 3860.33,4298.38 ; 4092.57,4746.64 4092.57,6901.52 ; -1094.8,3801.1 4409.91,3801.1 4409.91,4298.38 -1094.8,4298.38 -1094.8,3801.1 ; -1048.99,4746.64 4642.15,4746.64 4642.15,6901.52 -1048.99,6901.52 -1048.99,4746.64
  text "Drill Table: Top Layer to Bottom Layer" at -969.67,6950.88 h80
  text "Symbol" at -949.54,6785.49 h96
  text "Hit Count" at -548.78,6785.49 h96
  text "Finished Hole Size" at -70.24,6785.49 h96
  text "Plated" at 778.51,6785.49 h96
  text "Hole Type" at 1124.03,6785.49 h96
  text "Physical Length" at 1624.24,6785.49 h96
  text "Rout Path Length" at 2373.42,6785.49 h96
  text "Drill Layer Pair" at 3176.53,6785.49 h96
  text "Tolerance" at 4142.3,6785.49 h96
  text "16" at -548.78,6619.73 h80
  text "7.87mil (0.200mm)" at -70.24,6619.73 h80
  text "PTH" at 778.51,6619.73 h80
  text "Round" at 1124.03,6619.73 h80
  text "-" at 1624.24,6619.73 h80
  text "-" at 2373.42,6619.73 h80
  text "Top Layer - Bottom Layer" at 3176.53,6619.73 h80
  text "+0/-7.874mil" at 4142.3,6619.73 h80
  text "B" at -984.4,6604.74 h73.67
  text "8" at -1204.47,6594.48 h80
  text "74" at -548.78,6453.97 h80
  text "8.00mil (0.203mm)" at -70.24,6453.97 h80
  text "PTH" at 778.51,6453.97 h80
  text "Round" at 1124.03,6453.97 h80
  text "-" at 1624.24,6453.97 h80
  text "-" at 2373.42,6453.97 h80
  text "Top Layer - Bottom Layer" at 3176.53,6453.97 h80
  text "+0/-8mil" at 4142.3,6453.97 h80
  text "8" at -1204.47,6439.15 h80
  text "C" at -984.4,6438.98 h73.67
  text "62" at -548.78,6288.21 h80
  text "10.00mil (0.254mm)" at -70.24,6288.21 h80
  text "PTH" at 778.51,6288.21 h80
  text "Round" at 1124.03,6288.21 h80
  text "-" at 1624.24,6288.21 h80
  text "-" at 2373.42,6288.21 h80
  text "Top Layer - Bottom Layer" at 3176.53,6288.21 h80
  text "+0/-10mil" at 4142.3,6288.21 h80
  text "D" at -984.4,6273.22 h73.67
  text "8" at -1204.47,6265.42 h80
  text "510" at -548.78,6122.45 h80
  text "12.20mil (0.310mm)" at -70.24,6122.45 h80
  text "PTH" at 778.51,6122.45 h80
  text "Round" at 1124.03,6122.45 h80
  text "-" at 1624.24,6122.45 h80
  text "-" at 2373.42,6122.45 h80
  text "Top Layer - Bottom Layer" at 3176.53,6122.45 h80
  text "+0/-12.2mil" at 4142.3,6122.45 h80
  text "E" at -984.4,6107.46 h73.67
  text "8" at -1204.47,6106.3 h80
  text "6" at -548.78,5956.69 h80
  text "23.62mil (0.600mm)" at -70.24,5956.69 h80
  text "PTH" at 778.51,5956.69 h80
  text "Round" at 1124.03,5956.69 h80
  text "-" at 1624.24,5956.69 h80
  text "-" at 2373.42,5956.69 h80
  text "Top Layer - Bottom Layer" at 3176.53,5956.69 h80
  text "+/-3mil" at 4142.3,5956.69 h80
  text "G" at -984.4,5941.7 h73.67
  text "2" at -548.78,5790.93 h80
  text "23.62mil (0.600mm)" at -70.24,5790.93 h80
  text "PTH" at 778.51,5790.93 h80
  text "Slot" at 1124.03,5790.93 h80
  text "51.18mil (1.300mm)" at 1624.24,5790.93 h80
  text "27.56mil (0.700mm)" at 2373.42,5790.93 h80
  text "Top Layer - Bottom Layer" at 3176.53,5790.93 h80
  text "+/-3mil" at 4142.3,5790.93 h80
  text "F" at -984.4,5775.94 h73.67
  text "2" at -548.78,5625.17 h80
  text "33.47mil (0.850mm)" at -70.24,5625.17 h80
  text "PTH" at 778.51,5625.17 h80
  text "Round" at 1124.03,5625.17 h80
  text "-" at 1624.24,5625.17 h80
  text "-" at 2373.42,5625.17 h80
  text "Top Layer - Bottom Layer" at 3176.53,5625.17 h80
  text "+/-3mil" at 4142.3,5625.17 h80
  text "H" at -984.4,5610.18 h73.67
  text "4" at -548.78,5459.41 h80
  text "40.00mil (1.016mm)" at -70.24,5459.41 h80
  text "PTH" at 778.51,5459.41 h80
  text "Round" at 1124.03,5459.41 h80
  text "-" at 1624.24,5459.41 h80
  text "-" at 2373.42,5459.41 h80
  text "Top Layer - Bottom Layer" at 3176.53,5459.41 h80
  text "+/-3mil" at 4142.3,5459.41 h80
  text "I" at -972.12,5444.42 h73.67
  text "6" at -548.78,5293.65 h80
  text "40.16mil (1.020mm)" at -70.24,5293.65 h80
  text "NPTH" at 778.51,5293.65 h80
  text "Round" at 1124.03,5293.65 h80
  text "-" at 1624.24,5293.65 h80
  text "-" at 2373.42,5293.65 h80
  text "Top Layer - Bottom Layer" at 3176.53,5293.65 h80
  text "+/-2mil" at 4142.3,5293.65 h80
  text "J" at -984.4,5278.66 h73.67
  text "1" at -548.78,5127.89 h80
  text "80.00mil (2.032mm)" at -70.24,5127.89 h80
  text "PTH" at 778.51,5127.89 h80
  text "Round" at 1124.03,5127.89 h80
  text "-" at 1624.24,5127.89 h80
  text "-" at 2373.42,5127.89 h80
  text "Top Layer - Bottom Layer" at 3176.53,5127.89 h80
  text "+/-3mil" at 4142.3,5127.89 h80
  text "K" at -984.4,5112.9 h73.67
  text "8" at -548.78,4962.13 h80
  text "118.11mil (3.000mm)" at -70.24,4962.13 h80
  text "PTH" at 778.51,4962.13 h80
  text "Round" at 1124.03,4962.13 h80
  text "-" at 1624.24,4962.13 h80
  text "-" at 2373.42,4962.13 h80
  text "Top Layer - Bottom Layer" at 3176.53,4962.13 h80
  text "+/-3mil" at 4142.3,4962.13 h80
  text "L" at -984.4,4947.14 h73.67
  text "691 Total" at -548.78,4796.37 h80
  text "Slot definitions :" at -949.54,4680.34 h80
  text "Rout Path Length" at -348.58,4680.34 h80
  text "= Calculated from tool start centre position to tool end centre position." at 287.52,4680.34 h80
  text "Physical Length" at -348.58,4614.04 h80
  text "= Rout Path Length + Tool Size = Slot length as defined in the PCB layout" at 240.09,4614.04 h80
  text "Drill Table: Layer 1 To Layer 2" at -1089.09,4331.28 h80
  text "Symbol" at -995.35,4182.34 h96
  text "Hit Count" at -594.59,4182.34 h96
  text "Finished Hole Size" at -116.05,4182.34 h96
  text "Plated" at 732.7,4182.34 h96
  text "Hole Type" at 1078.22,4182.34 h96
  text "Physical Length" at 1578.43,4182.34 h96
  text "Rout Path Length" at 2324.62,4182.34 h96
  text "Drill Layer Pair" at 3127.73,4182.34 h96
  text "Tolerance" at 3910.05,4182.34 h96
  text "981" at -594.59,4016.58 h80
  text "5.90mil (0.150mm)" at -116.05,4016.58 h80
  text "PTH" at 732.7,4016.58 h80
  text "Round" at 1078.22,4016.58 h80
  text "-" at 1578.43,4016.58 h80
  text "-" at 2324.62,4016.58 h80
  text "Top Layer - L2_GND" at 3127.73,4016.58 h80
  text "+0/-5.9mil" at 3910.05,4016.58 h80
  text "8" at -1206.55,4005.41 h80
  text "A" at -1030.21,4001.6 h73.67
  text "981 Total" at -594.59,3850.83 h80
  text ".Layer_Name" at -423,-1328.72 h60
M17 Embedded Cavity:
  text ".Layer_Name" at -423,-1328.72 h60
M18 Embedded Assembly:
  text ".Layer_Name" at -423,-1328.72 h60
M19 Embedded Keepout:
  text ".Layer_Name" at -423,-1328.72 h60

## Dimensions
-13.18,-12.02 to -78.99,-64.55 on M2 Board Dimensions
236.54,127.3 to 0,0 on M2 Board Dimensions
236.54,0 to 556.54,0 on M2 Board Dimensions
0,0 to 236.54,0 on M2 Board Dimensions
0,2695.13 to 2165.35,2695.12 on M2 Board Dimensions
0,0 to 0,2695.13 on M2 Board Dimensions
-1000,-870.23 to 0,-870.23 on M2 Board Dimensions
